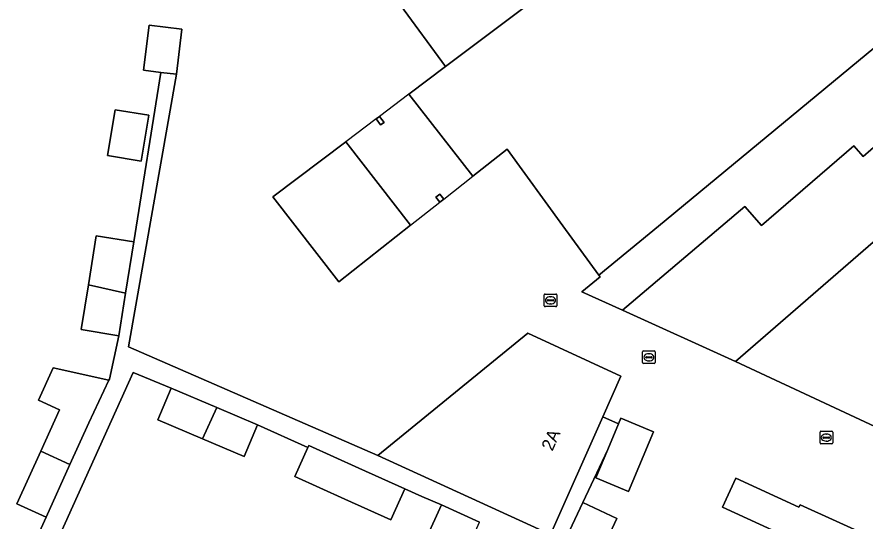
# Model space of a CAD drawing. Extents: x 161838 to 162344, y 381620 to 382160.
# Drawn here: x 162041.7 to 162108.9, y 381833 to 381872.9 of the extents above; entities that cross this region are included whole.
import ezdxf

# ---------------------------------------------------------------- set-up
doc = ezdxf.new("R2010")
doc.units = 0
for name, color, linetype in [('IMGEO_Erf', 7, 'Continuous'), ('IMGEO_Kolk', 7, 'Continuous'), ('IMGEO_Pand', 7, 'Continuous'), ('IMGEO_Pand_nummerreeks', 7, 'Continuous'), ('IMGEO_Pand_overbouw', 7, 'Continuous'), ('IMGEO_Rioolput', 7, 'Continuous'), ('IMGEO_Voetpad_open', 7, 'Continuous')]:
    doc.layers.add(name, color=color, linetype=linetype)

msp = doc.modelspace()

# ---------------------------------------------------------------- linework, layer by layer
at = {"layer": 'IMGEO_Erf'}
for points in [[(162114.735, 381838.122), (162098.619, 381845.654), (162089.659, 381849.709), (162086.443, 381851.165), (162087.873, 381852.364), (162087.786, 381852.483), (162084.93, 381856.406), (162080.51, 381862.474), (162077.805, 381860.339), (162072.729, 381866.818), (162075.631, 381869.008), (162072.058, 381873.873), (162069.099, 381877.903), (162075.32, 381882.188), (162072.015, 381887.691)], [(162043.078, 381831.282), (162044.004, 381833.315), (162041.684, 381834.361), (162043.565, 381838.533), (162045.051, 381841.828), (162043.389, 381842.577), (162044.549, 381845.148), (162048.967, 381844.175), (162049.003, 381844.251), (162049.755, 381847.692), (162046.779, 381848.168), (162047.347, 381851.719), (162047.969, 381855.609), (162050.946, 381855.133), (162053.093, 381868.548), (162051.715, 381868.716), (162052.149, 381872.288), (162054.745, 381871.972), (162054.311, 381868.4), (162050.525, 381846.815), (162070.262, 381838.192), (162082.156, 381847.89), (162089.518, 381844.483), (162088.092, 381841.274), (162089.341, 381840.719), (162089.525, 381841.156), (162092.118, 381840.064), (162090.133, 381835.35), (162087.54, 381836.442), (162088.485, 381838.686), (162086.508, 381834.485), (162089.21, 381833.214), (162087.745, 381830.099)], [(162074.11, 381831.62), (162075.323, 381834.28), (162073.757, 381834.949), (162072.401, 381835.563), (162071.289, 381833.107), (162067.668, 381834.747), (162063.706, 381836.542), (162064.739, 381838.822), (162060.736, 381840.635), (162059.68, 381838.131), (162056.395, 381839.517), (162052.834, 381841.02), (162053.89, 381843.523), (162050.892, 381844.787), (162045.124, 381832.027)], [(162102.461, 381831.87), (162097.576, 381834.098), (162098.622, 381836.392), (162103.629, 381834.109), (162103.716, 381834.299), (162109.724, 381831.56)]]:
    msp.add_lwpolyline(points, dxfattribs=at)
for points in [[(162049.472, 381865.595), (162052.121, 381865.149), (162051.511, 381861.526), (162048.862, 381861.973)], [(162070.405, 381865.065), (162070.765, 381864.59), (162070.496, 381864.387), (162070.136, 381864.862)], [(162067.741, 381863.055), (162072.872, 381856.443), (162067.187, 381851.955), (162061.967, 381858.698)], [(162075.191, 381858.909), (162075.499, 381858.518), (162075.186, 381858.271), (162074.878, 381858.662)]]:
    msp.add_lwpolyline(points, close=True, dxfattribs=at)
at = {"layer": 'IMGEO_Kolk'}
for p, q in [((162091.245, 381845.554), (162091.245, 381846.406)), ((162091.32, 381846.48), (162092.172, 381846.48)), ((162092.246, 381846.406), (162092.246, 381845.554)), ((162091.504, 381845.974), (162091.504, 381845.986)), ((162091.942, 381845.937), (162091.544, 381845.937)), ((162091.547, 381846.023), (162091.945, 381846.023)), ((162091.756, 381845.7), (162091.731, 381845.7)), ((162091.733, 381846.26), (162091.758, 381846.26)), ((162091.988, 381845.986), (162091.988, 381845.974)), ((162092.172, 381845.48), (162091.32, 381845.48)), ((162105.303, 381839.192), (162105.303, 381840.044)), ((162105.378, 381840.118), (162106.23, 381840.118)), ((162105.562, 381839.612), (162105.562, 381839.624)), ((162105.605, 381839.661), (162106.003, 381839.661)), ((162105.791, 381839.898), (162105.816, 381839.898)), ((162106.046, 381839.624), (162106.046, 381839.612)), ((162106.304, 381840.044), (162106.304, 381839.192)), ((162106.23, 381839.118), (162105.378, 381839.118)), ((162106, 381839.575), (162105.602, 381839.575)), ((162105.814, 381839.338), (162105.789, 381839.338))]:
    msp.add_line(p, q, dxfattribs=at)
for points in [[(162091.245, 381845.554), (162091.245, 381846.406)], [(162091.32, 381846.48), (162092.172, 381846.48)], [(162092.246, 381846.406), (162092.246, 381845.554)], [(162092.172, 381845.48), (162091.32, 381845.48)], [(162105.303, 381839.192), (162105.303, 381840.044)], [(162105.378, 381840.118), (162106.23, 381840.118)], [(162106.304, 381840.044), (162106.304, 381839.192)], [(162106.23, 381839.118), (162105.378, 381839.118)]]:
    msp.add_lwpolyline(points, dxfattribs=at)
for centre, radius, start, end in [((162091.322, 381846.404), 0.0765, 91.55205, 178.44795), ((162091.322, 381846.404), 0.0765, 91.55205, 178.44795), ((162092.17, 381846.404), 0.0765, 1.55205, 88.44795), ((162092.17, 381846.404), 0.0765, 1.55205, 88.44795), ((162091.544, 381845.983), 0.0403, 85.87752, 175.75265), ((162091.541, 381845.973), 0.0366, 178.93798, 274.71019), ((162091.945, 381845.98), 0.043, 264.86636, 352.45326), ((162091.949, 381845.985), 0.0386, 1.73085, 96.63898), ((162091.322, 381845.556), 0.0765, 181.55205, 268.44795), ((162091.322, 381845.556), 0.0765, 181.55205, 268.44795), ((162092.17, 381845.556), 0.0765, 271.55205, 358.44795), ((162092.17, 381845.556), 0.0765, 271.55205, 358.44795), ((162105.38, 381840.042), 0.0765, 91.55205, 178.44795), ((162105.38, 381840.042), 0.0765, 91.55205, 178.44795), ((162105.602, 381839.621), 0.0403, 85.87752, 175.75265), ((162105.599, 381839.611), 0.0366, 178.93798, 274.71019), ((162106.003, 381839.618), 0.043, 264.86636, 352.45326), ((162106.007, 381839.623), 0.0386, 1.73085, 96.63898), ((162106.228, 381840.042), 0.0765, 1.55205, 88.44795), ((162106.228, 381840.042), 0.0765, 1.55205, 88.44795), ((162105.38, 381839.194), 0.0765, 181.55205, 268.44795), ((162105.38, 381839.194), 0.0765, 181.55205, 268.44795), ((162106.228, 381839.194), 0.0765, 271.55205, 358.44795), ((162106.228, 381839.194), 0.0765, 271.55205, 358.44795)]:
    msp.add_arc(centre, radius, start, end, dxfattribs=at)
for centre, major_axis, ratio, start_param, end_param in [((162091.732, 381845.98), (-0.387, 0.002), 0.722429, 4.712389, 7.853982), ((162091.757, 381845.98), (-0.39, 0.002), 0.717154, 1.570796, 4.712389), ((162105.79, 381839.618), (-0.387, 0.002), 0.722429, 4.712389, 7.853982), ((162105.815, 381839.618), (-0.39, 0.002), 0.717154, 1.570796, 4.712389)]:
    msp.add_ellipse(centre, major_axis=major_axis, ratio=ratio, start_param=start_param, end_param=end_param, dxfattribs=at)
at = {"layer": 'IMGEO_Pand'}
for points in [[(162099.686, 381886.922), (162100.322, 381887.406), (162097.662, 381892.16), (162084.695, 381883.046), (162072.058, 381873.873), (162075.631, 381869.008), (162083.544, 381874.978)], [(162099.686, 381886.922), (162083.544, 381874.978), (162075.631, 381869.008), (162072.729, 381866.818), (162077.805, 381860.339), (162080.51, 381862.474), (162084.93, 381856.406), (162087.786, 381852.483), (162092.498, 381856.374), (162110.94, 381871.605), (162111.059, 381871.814)], [(162054.745, 381871.972), (162052.149, 381872.288), (162051.715, 381868.716), (162053.093, 381868.548), (162054.311, 381868.4)], [(162087.786, 381852.483), (162087.873, 381852.364), (162086.443, 381851.165), (162089.659, 381849.709), (162099.355, 381857.936), (162100.673, 381856.414), (162107.979, 381862.737), (162108.715, 381861.887), (162114.795, 381867.156), (162110.94, 381871.605), (162092.498, 381856.374)], [(162118.49, 381862.892), (162114.795, 381867.156), (162108.715, 381861.887), (162107.979, 381862.737), (162100.673, 381856.414), (162099.355, 381857.936), (162089.659, 381849.709), (162098.619, 381845.654), (162109.895, 381855.443)], [(162052.121, 381865.149), (162049.472, 381865.595), (162048.862, 381861.973), (162051.511, 381861.526)], [(162070.405, 381865.065), (162070.136, 381864.862), (162070.496, 381864.387), (162070.765, 381864.59)], [(162067.741, 381863.055), (162061.967, 381858.698), (162067.187, 381851.955), (162072.872, 381856.443)], [(162114.735, 381838.122), (162121.682, 381847.505), (162120.737, 381848.595), (162126.698, 381853.761), (162118.49, 381862.892), (162109.895, 381855.443), (162098.619, 381845.654)], [(162075.186, 381858.271), (162075.499, 381858.518), (162075.191, 381858.909), (162074.878, 381858.662)], [(162047.347, 381851.719), (162050.292, 381851.046), (162050.946, 381855.133), (162047.969, 381855.609)], [(162047.347, 381851.719), (162046.779, 381848.168), (162049.755, 381847.692), (162050.292, 381851.046)], [(162088.092, 381841.274), (162089.518, 381844.483), (162082.156, 381847.89), (162070.262, 381838.192), (162083.94, 381831.933)], [(162047.371, 381840.782), (162048.967, 381844.175), (162044.549, 381845.148), (162043.389, 381842.577), (162045.051, 381841.828), (162043.565, 381838.533), (162045.884, 381837.484)], [(162057.515, 381841.994), (162053.89, 381843.523), (162052.834, 381841.02), (162056.395, 381839.517)], [(162057.515, 381841.994), (162056.395, 381839.517), (162059.68, 381838.131), (162060.736, 381840.635)], [(162092.118, 381840.064), (162089.525, 381841.156), (162089.341, 381840.719), (162088.485, 381838.686), (162087.54, 381836.442), (162090.133, 381835.35)], [(162068.778, 381837.204), (162064.818, 381838.997), (162064.739, 381838.822), (162063.706, 381836.542), (162067.668, 381834.747), (162071.289, 381833.107), (162072.401, 381835.563)], [(162045.884, 381837.484), (162043.565, 381838.533), (162041.684, 381834.361), (162044.004, 381833.315)], [(162107.516, 381826.718), (162109.724, 381831.56), (162103.716, 381834.299), (162103.629, 381834.109), (162098.622, 381836.392), (162097.576, 381834.098), (162102.461, 381831.87), (162101.387, 381829.514)], [(162077.126, 381830.245), (162078.33, 381832.909), (162075.323, 381834.28), (162074.11, 381831.62)], [(162085.027, 381831.338), (162087.745, 381830.099), (162089.21, 381833.214), (162086.508, 381834.485)]]:
    msp.add_lwpolyline(points, close=True, dxfattribs=at)
at = {"layer": 'IMGEO_Pand_overbouw'}
msp.add_lwpolyline([(162075.186, 381858.271), (162074.878, 381858.662), (162075.191, 381858.909), (162075.499, 381858.518), (162077.805, 381860.339), (162072.729, 381866.818), (162070.405, 381865.065), (162070.765, 381864.59), (162070.496, 381864.387), (162070.136, 381864.862), (162067.741, 381863.055), (162072.872, 381856.443)], close=True, dxfattribs=at)
at = {"layer": 'IMGEO_Rioolput'}
for p, q in [((162083.453, 381850.064), (162083.453, 381850.916)), ((162083.528, 381850.99), (162084.38, 381850.99)), ((162083.712, 381850.484), (162083.712, 381850.496)), ((162084.15, 381850.447), (162083.752, 381850.447)), ((162083.755, 381850.533), (162084.153, 381850.533)), ((162083.941, 381850.77), (162083.966, 381850.77)), ((162084.196, 381850.496), (162084.196, 381850.484)), ((162084.454, 381850.916), (162084.454, 381850.064)), ((162084.38, 381849.99), (162083.528, 381849.99)), ((162083.964, 381850.21), (162083.939, 381850.21))]:
    msp.add_line(p, q, dxfattribs=at)
for points in [[(162083.453, 381850.064), (162083.453, 381850.916)], [(162083.528, 381850.99), (162084.38, 381850.99)], [(162084.454, 381850.916), (162084.454, 381850.064)], [(162084.38, 381849.99), (162083.528, 381849.99)]]:
    msp.add_lwpolyline(points, dxfattribs=at)
for centre, radius, start, end in [((162083.53, 381850.914), 0.0765, 91.55205, 178.44795), ((162083.53, 381850.914), 0.0765, 91.55205, 178.44795), ((162083.752, 381850.493), 0.0403, 85.87752, 175.75265), ((162083.749, 381850.483), 0.0366, 178.93798, 274.71019), ((162084.153, 381850.49), 0.043, 264.86636, 352.45326), ((162084.157, 381850.495), 0.0386, 1.73085, 96.63898), ((162084.378, 381850.914), 0.0765, 1.55205, 88.44795), ((162084.378, 381850.914), 0.0765, 1.55205, 88.44795), ((162083.53, 381850.066), 0.0765, 181.55205, 268.44795), ((162083.53, 381850.066), 0.0765, 181.55205, 268.44795), ((162084.378, 381850.066), 0.0765, 271.55205, 358.44795), ((162084.378, 381850.066), 0.0765, 271.55205, 358.44795)]:
    msp.add_arc(centre, radius, start, end, dxfattribs=at)
for centre, major_axis, ratio, start_param, end_param in [((162083.94, 381850.49), (-0.387, 0.002), 0.722429, 4.712389, 7.853982), ((162083.965, 381850.49), (-0.39, 0.002), 0.717154, 1.570796, 4.712389)]:
    msp.add_ellipse(centre, major_axis=major_axis, ratio=ratio, start_param=start_param, end_param=end_param, dxfattribs=at)
at = {"layer": 'IMGEO_Voetpad_open'}
for points in [[(162085.027, 381831.338), (162086.508, 381834.485), (162088.485, 381838.686), (162089.341, 381840.719), (162088.092, 381841.274), (162083.94, 381831.933), (162070.262, 381838.192), (162050.525, 381846.815), (162054.311, 381868.4), (162053.093, 381868.548), (162050.946, 381855.133), (162050.292, 381851.046), (162049.755, 381847.692), (162049.003, 381844.251), (162048.967, 381844.175), (162047.371, 381840.782), (162045.884, 381837.484), (162044.004, 381833.315), (162043.078, 381831.282)], [(162045.124, 381832.027), (162050.892, 381844.787), (162053.89, 381843.523), (162057.515, 381841.994), (162060.736, 381840.635), (162064.739, 381838.822), (162064.818, 381838.997), (162068.778, 381837.204), (162072.401, 381835.563), (162073.757, 381834.949), (162075.323, 381834.28), (162078.33, 381832.909)]]:
    msp.add_lwpolyline(points, dxfattribs=at)

# ---------------------------------------------------------------- texts
at = {"layer": 'IMGEO_Pand_nummerreeks'}
msp.add_text('2A', height=1, rotation=66.03912, dxfattribs=at).set_placement((162084.099, 381838.496))

doc.saveas('drawing.dxf')
